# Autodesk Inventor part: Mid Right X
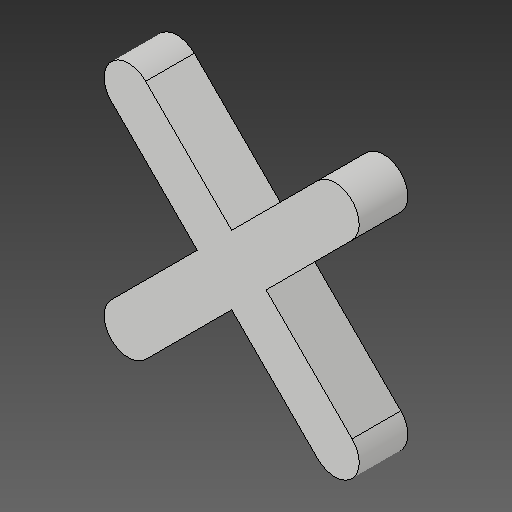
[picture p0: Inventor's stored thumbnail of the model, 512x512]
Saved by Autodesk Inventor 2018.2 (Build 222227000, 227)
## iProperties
Created: 2018-03
Part Number: Mid Right X
Material: Generic
Document SubType Name: Modeling
Designer: PeterMaxwell-Stewart
Mass: 1.57135 g
Surface Area: 12.8562 cm^2
Volume: 1.57135 cm^3
Density: 1 g/cm^3
Appearance: Default
Author: PeterMaxwell-Stewart
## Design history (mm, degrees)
derived "O's and X's.ipt"
feature "Mid Right X::O's and X's.ipt" dims "d0" = 10
tag "TaggingFeature1"
body "Solid1"
